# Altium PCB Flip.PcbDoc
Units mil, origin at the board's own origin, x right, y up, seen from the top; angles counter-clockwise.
Board outline 1094.88 x 2000 mil, 4 copper layers (Top Layer, GND, PWR, Bottom Layer), stack 23.756 mil thick; 97 components, 90 nets, 414 pads, 53 vias.
Unrouted connection lines stored in the file: 200.
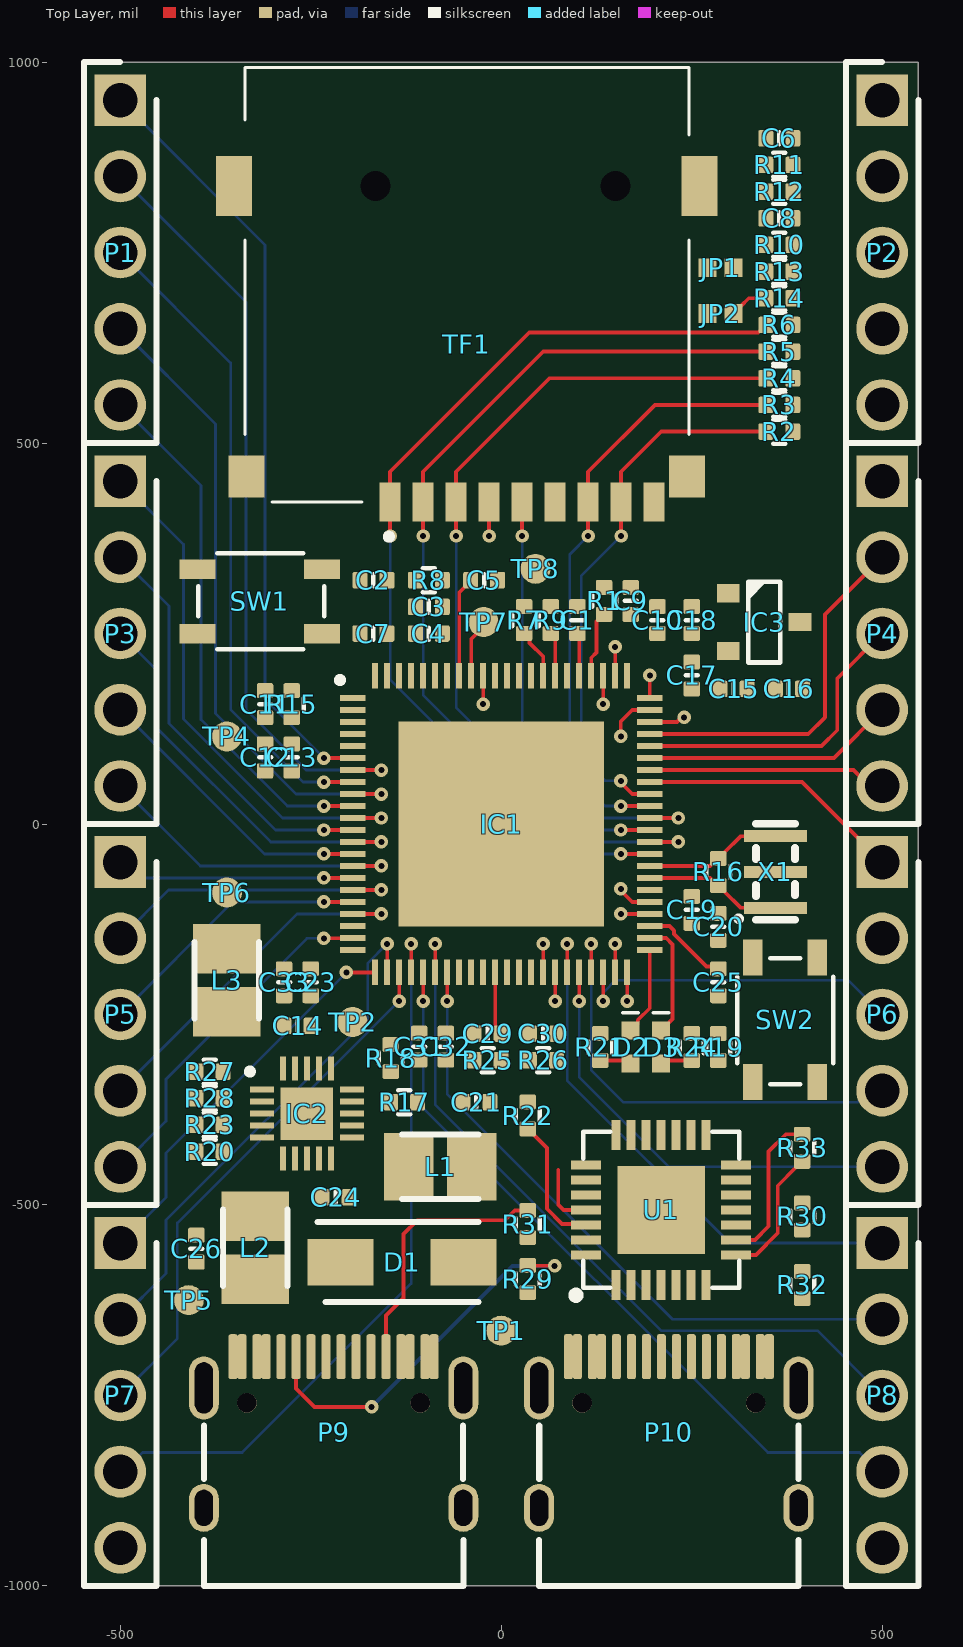
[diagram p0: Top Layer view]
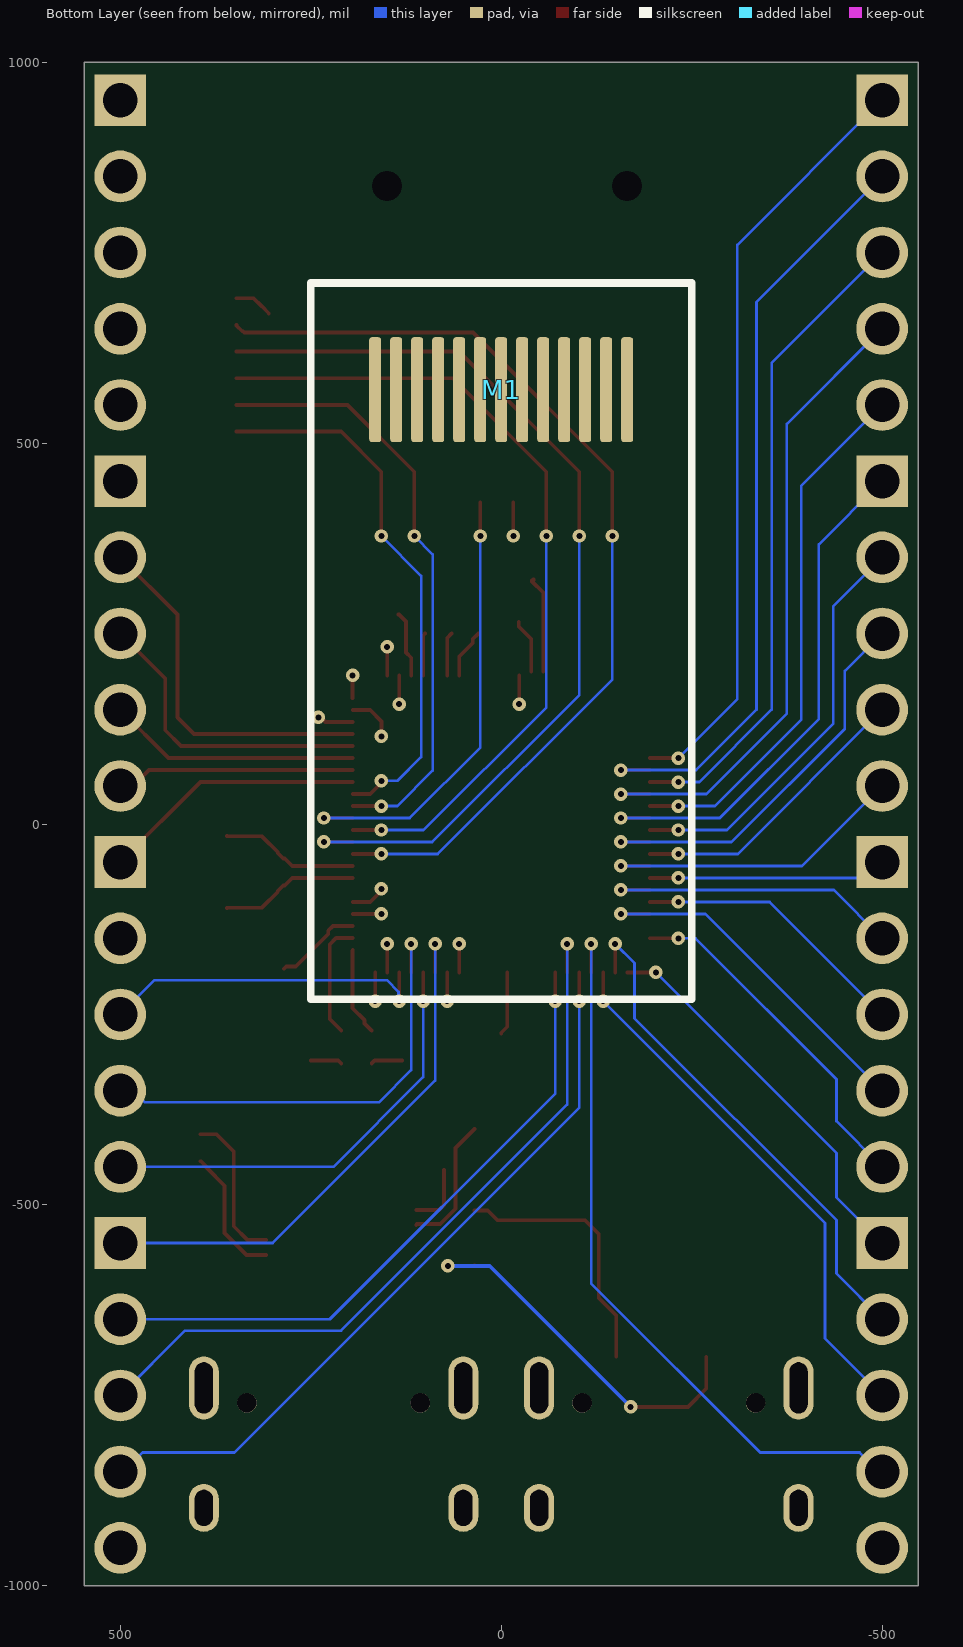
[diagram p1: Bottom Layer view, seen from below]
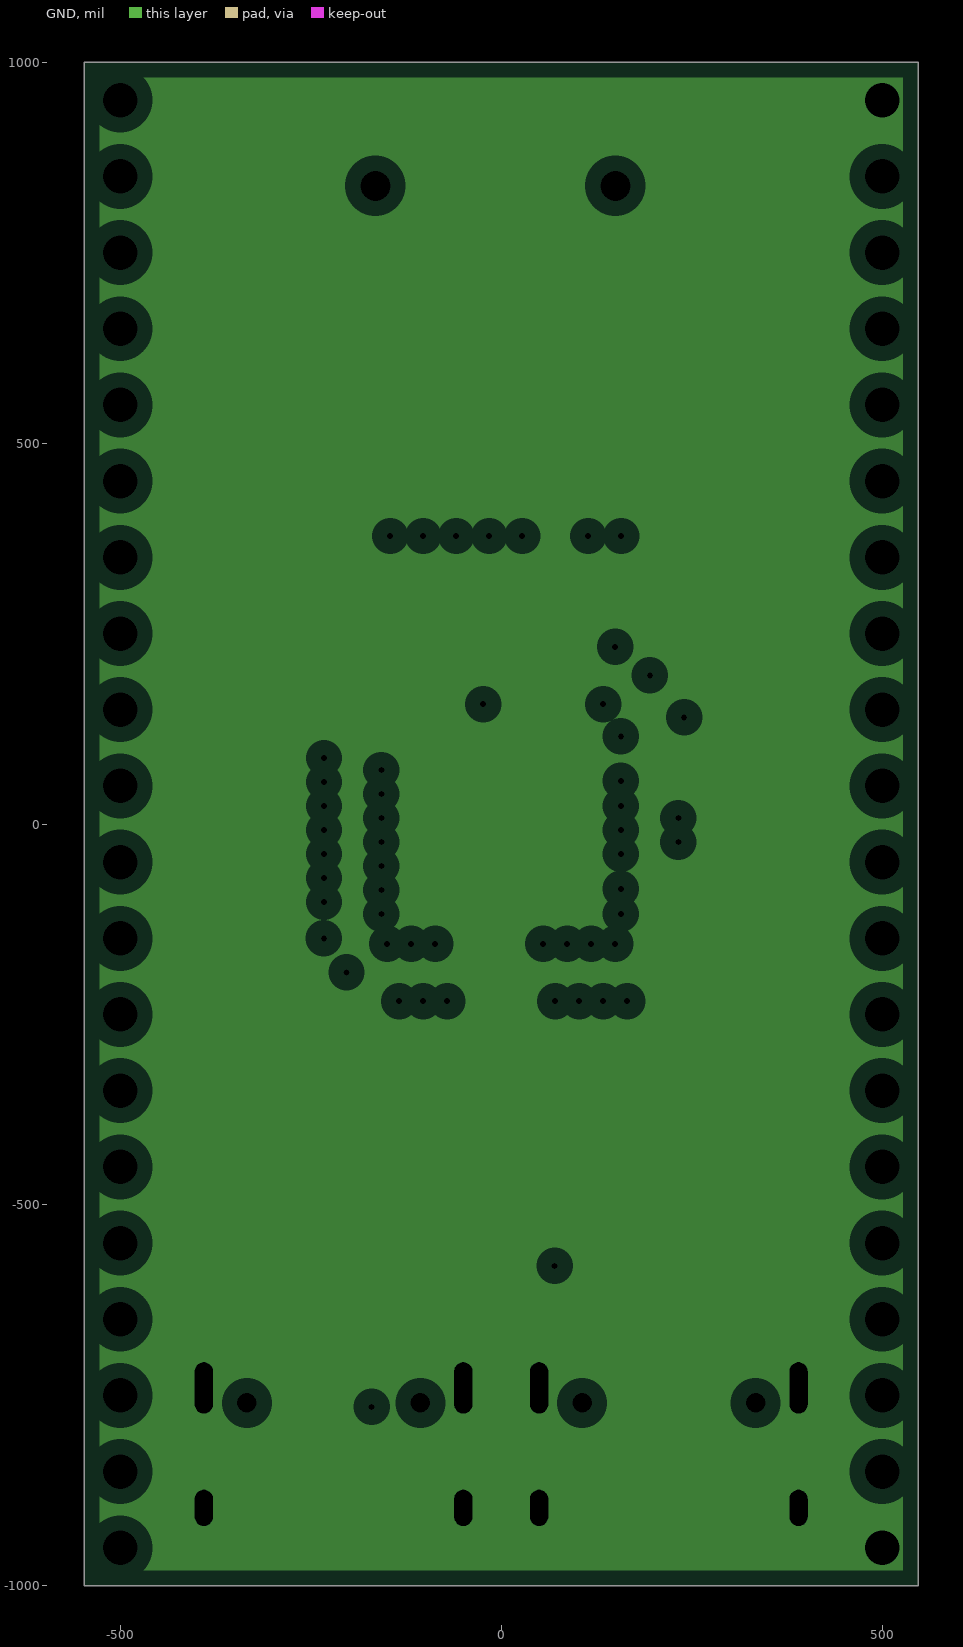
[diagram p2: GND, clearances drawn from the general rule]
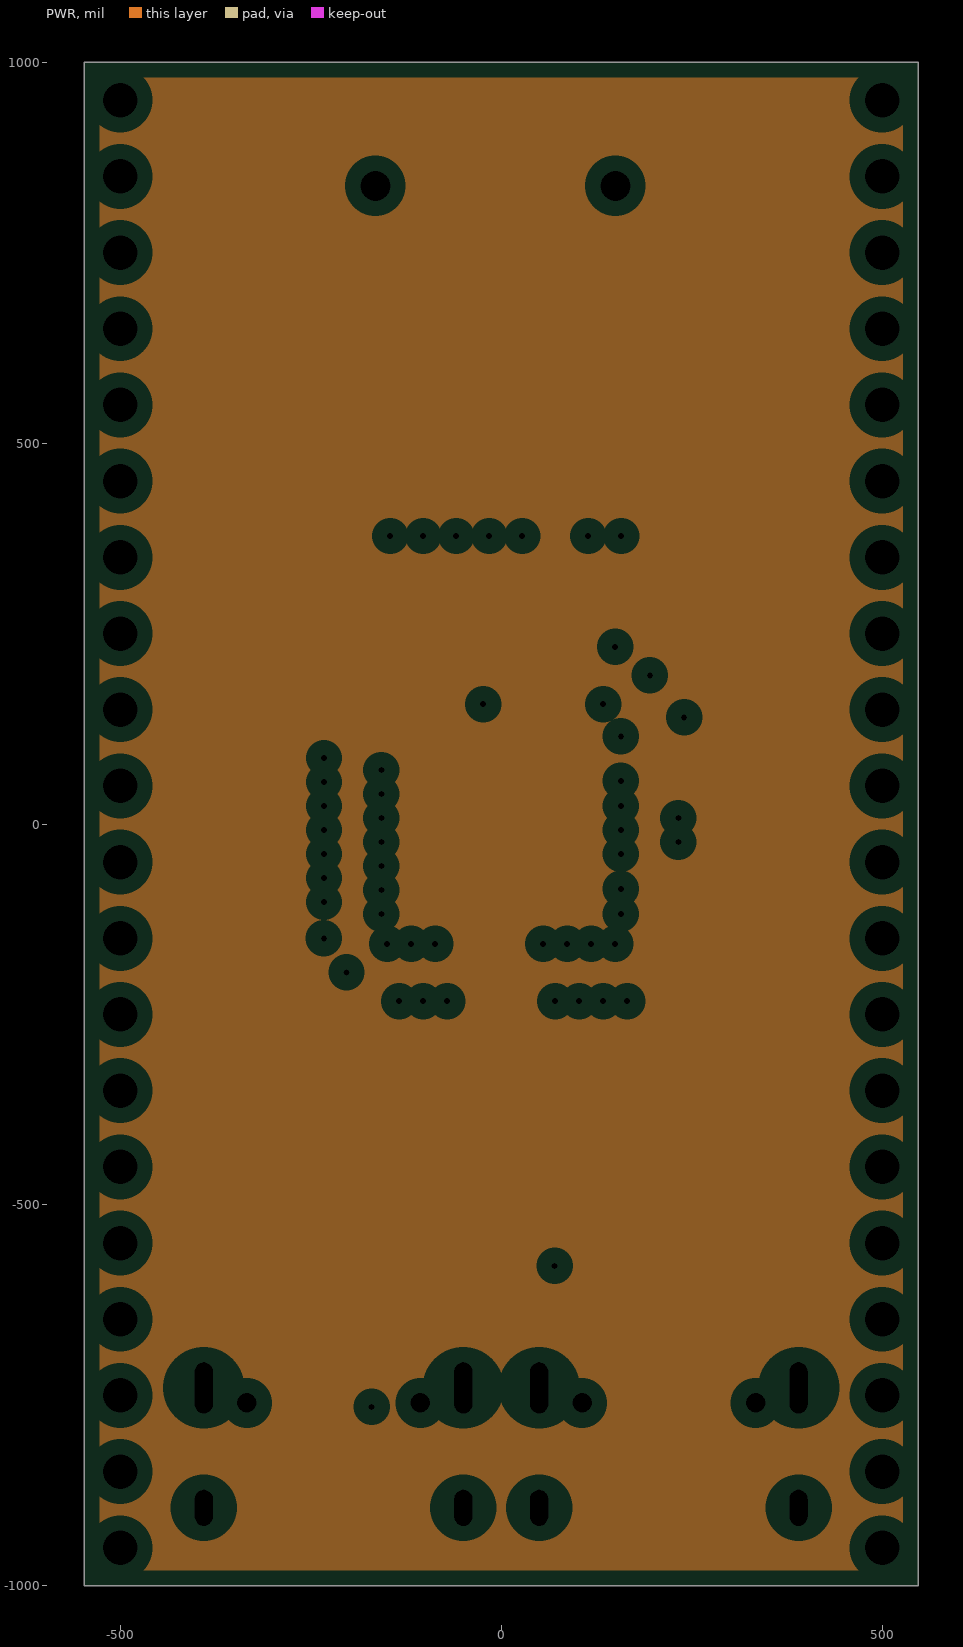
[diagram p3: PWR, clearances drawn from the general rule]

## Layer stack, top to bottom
Top Solder: solder mask 0.4, Solder Resist, Dk 3.5
Top Layer: signal copper 1.4
Dielectric 2: prepreg 2.8, PP-006, Dk 4.1
GND: plane copper 1.378, net GND
Dielectric 1: dielectric 12.6, FR-4, Dk 4.8
PWR: plane copper 1.378
Dielectric 3: prepreg 2.8, PP-006, Dk 4.1
Bottom Layer: signal copper 1.4
Bottom Solder: solder mask 0.4, Solder Resist, Dk 3.5

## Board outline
-547.44,-1000 547.44,-1000 547.44,1000 -547.44,1000

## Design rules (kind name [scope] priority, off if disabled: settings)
Clearance [All] p1: gap=10 ignorepadtopadclearanceinfootprint=FALSE except(0: Arc-Hole Track-Hole SMDPad-Hole THPad-Hole Via-Hole Fill-Hole Poly-Hole Region-Hole Text-Hole)
DiffPairsRouting [All] p1: maxlimit=10 minlimit=10 mostfreqgap=10 toplayer_minwidth=15 toplayer_maxwidth=15 toplayer_prefwidth=15 bottomlayer_minwidth=15 bottomlayer_maxwidth=15 bottomlayer_prefwidth=15 maxuncoupledlength=500
PlaneClearance [All] p1: clearance=20
PlaneConnect [All] p1: planeconnectstyle=Relief reliefexpansion=20 reliefentries=4 reliefconductorwidth=10 reliefairgap=10
PolygonConnect [All] p1: connectstyle=Relief reliefconductorwidth=10 reliefentries=4 polygonreliefangle="90 Angle" airgapwidth=10
RoutingVias [All] p1: holewidth=7.87 width=17.72 viastyle="Through Hole" minholewidth=7.87 minwidth=17.72 maxholewidth=7.87 maxwidth=17.72
SolderMaskExpansion [All] p1: expansion=4 istentingtop=FALSE
Width [All] p1: maxlimit=100 minlimit=3.5 preferedwidth=3.5
27 further rules are at their usual default settings.

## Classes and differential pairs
differential pair USB: +USB_P -USB_N
differential pair USB_CP: +USB_CP_P -USB_CP_N

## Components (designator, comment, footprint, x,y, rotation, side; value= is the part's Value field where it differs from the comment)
C1 "100nF" CAP-0402 100,267.72 r270 top
C2 "10uF" CAP-0402 -167.72,320 r180 top
C3 "100nF" CAP-0402 -95,285 r180 top
C4 "10uF" CAP-0402 -95,250 r0 top
C5 "1uF" CAP-0402 -22.28,320 r180 top
C6 "10uF" CAP-0402 365,900 r0 top
C7 "100nF" CAP-0402 -167.72,250 r180 top
C8 "10uF" CAP-0402 365,795 r0 top
C9 "100nF" CAP-0402 170,292.72 r90 top
C10 "10uF" CAP-0402 205,267.72 r270 top
C11 "1uF" CAP-0402 -310,157.28 r90 top
C12 "10uF" CAP-0402 -310,87.28 r90 top
C13 "100nF" CAP-0402 -275,87.28 r90 top
C14 "100nF" CAP-0402 -267.28,-265 r180 top
C15 "10uF" CAP-0402 305,177.28 r0 top
C16 "1uF" CAP-0402 377.72,177.28 r0 top
C17 "10uF" CAP-0402 250,195 r90 top
C18 "1uF" CAP-0402 250,267.72 r90 top
C19 "100nF" CAP-0402 250,-112.72 r90 top
C20 "10uF" CAP-0402 285,-135 r90 top
C21 "10uF" CAP-0402 -32.72,-365 r0 top
C23 "100nF" CAP-0402 -250,-207.72 r90 top
C24 "10uF" CAP-0402 -217.28,-490 r180 top
C25 "100nF" CAP-0402 285,-207.72 r90 top
C26 "10uF" CAP-0402 -400,-557.28 r270 top
C29 "100nF" CAP-0402 -17.72,-275 r0 top
C30 "100nF" CAP-0402 55,-275 r0 top
C31 "10uF" CAP-0402 -107.72,-292.28 r270 top
C32 "100nF" CAP-0402 -72.72,-292.28 r270 top
C33 "10uF" CAP-0402 -285,-207.72 r90 top
D1 "SS34" DO-214AC/SMA -130,-575 r0 top
D2 "RED" LED-0402 170,-292.72 r90 top
D3 "RED" LED-0402 210,-292.72 r90 top
IC1 "F1C200S" QFN88P_10X10mm 0,0 r0 top
IC2 "EA3036C" QFN3mmx3mm-20 -255,-380 r0 top
IC3 "XC6206P302MR-G" SOT-23-3 345,265 r180 top
JP1 "Select" 选择焊点-0402 288,730 r0 top
JP2 "Select" 选择焊点-0402 288,670 r0 top
L1 "2.2uH" L-1008 -80,-450 r0 top
L2 "2.2uH" L-1008 -322.72,-556.34 r270 top
L3 "2.2uH" L-1008 -360,-205 r90 top
M1 "OLED_12880" OLED_0.78INCH_12880 0,570 r90 bottom locked
P1 "HDR1x5" HDR1X5_2.54_180_BLANK -500,950 r270 top
P2 "HDR1x5" HDR1X5_2.54_180_BLANK 500,950 r270 top
P3 "HDR1x5" HDR1X5_2.54_180_BLANK -500,450 r270 top
P4 "HDR1x5" HDR1X5_2.54_180_BLANK 500,450 r270 top
P5 "HDR1x5" HDR1X5_2.54_180_BLANK -500,-50 r270 top
P6 "HDR1x5" HDR1X5_2.54_180_BLANK 500,-50 r270 top
P7 "HDR1x5" HDR1X5_2.54_180_BLANK -500,-550 r270 top
P8 "HDR1x5" HDR1X5_2.54_180_BLANK 500,-550 r270 top
P9 "TYPE-C-31-M-12" Type-C_16+4P -220,-798.36 r270 top
P10 "TYPE-C-31-M-12" Type-C_16+4P 220,-798.36 r270 top
R1 "10k" R-0402 135,292.72 r90 top
R2 "10k" R-0402 365,515 r0 top
R3 "10k" R-0402 365,550 r0 top
R4 "10k" R-0402 365,585 r0 top
R5 "10k" R-0402 365,620 r0 top
R6 "10k" R-0402 365,655 r0 top
R7 "0R" R-0402 30,267.72 r90 top
R8 "10k" R-0402 -95,320 r0 top
R9 "0R" R-0402 65,267.72 r90 top
R10 "10k" R-0402 365,760 r180 top
R11 "5.1k" R-0402 365,865 r180 top
R12 "560k" R-0402 365,830 r180 top
R13 "10k" R-0402 365,725 r180 top
R14 "10k" R-0402 365,690 r180 top
R15 "22R" R-0402 -275,157.28 r90 top
R16 "1M" R-0402 285,-62.99 r90 top
R17 "510k" R-0402 -127.28,-365 r0 top
R18 "110k" R-0402 -145,-307.28 r270 top
R19 "10k" R-0402 285,-292.72 r90 top
R20 "316k" R-0402 -382.72,-430 r180 top
R21 "5.1k" R-0402 130,-292.72 r270 top
R22 "200R" R-0402 35,-382.72 r270 top
R23 "100k" R-0402 -382.72,-395 r0 top
R24 "5.1k" R-0402 250,-292.72 r270 top
R25 "5.1k" R-0402 -17.72,-310 r0 top
R26 "5.1k" R-0402 55,-310 r0 top
R27 "100k" R-0402 -382.72,-325 r180 top
R28 "100k" R-0402 -382.72,-360 r0 top
R29 "56k" R-0402 35,-597.28 r90 top
R30 "5.1k" R-0402 395,-515 r90 top
R31 "5.1k" R-0402 35,-525 r270 top
R32 "5.1k" R-0402 395,-605 r90 top
R33 "10k" R-0402 395,-425 r270 top
SW1 "KEY" KEY-4P-4.2*3.4*2.5 -316.69,292.32 r180 top
SW2 "KEY" KEY-4P-4.2*3.4*2.5 372.68,-256.69 r90 top
TF1 "TF-01A" TF_1 -45,630 r90 top
TP1 "TestPoint" TestPoint 0,-665 r90 top
TP2 "TestPoint" TestPoint -195,-260 r90 top
TP4 "TestPoint" TestPoint -360,115 r90 top
TP5 "TestPoint" TestPoint -410,-625 r90 top
TP6 "TestPoint" TestPoint -360,-90 r90 top
TP7 "TestPoint" TestPoint -23,265 r90 top
TP8 "TestPoint" TestPoint 45,335 r90 top
U1 "CP2102" QFN28 210,-506.58 r90 top
X1 "24MHz" SMD3213-3P 360,-62.89 r90 top

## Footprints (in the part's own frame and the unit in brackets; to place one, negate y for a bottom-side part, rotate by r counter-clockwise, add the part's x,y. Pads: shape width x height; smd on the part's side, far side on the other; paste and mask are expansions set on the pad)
CAP-0402 [mm]
  rrect25% 0.5x0.55 smd: 1(-0.45,0) 2(0.45,0)
  silkscreen extent 0,-0.2 0,0.2, body extent -0.5,-0.25 0.5,0.25, height 0.6
DO-214AC/SMA [mm]
  rect 2.2x1.55 smd: 1(2.05,0) 2(-2.05,0)
  silkscreen extent -2.83,-1.33 2.55,1.33, body extent -2.55,-1.33 2.55,1.33, height 2.29
HDR1X5_2.54_180_BLANK [mm]
  rect 1.725x1.725 hole 1.15: 1(0,0)
  round 1.725 hole 1.15: 2(2.54,0) 3(5.08,0) 4(7.62,0) 5(10.16,0)
  silkscreen extent -1.27,-1.2 11.43,1.2
KEY-4P-4.2*3.4*2.5 [mm] "SKRPABE010"
  rect 1.2x0.65 smd: 1(-2.075,1.075) 1(2.075,1.075) 2(-2.075,-1.075) 2(2.075,-1.075)
  silkscreen extent -2.15,-1.6 2.05,1.6, body extent -2.35,-1.6 2.25,1.6, height 2.5
L-1008 [mm]
  rect 1.65x2.25 smd: 1(-1.05,0) 2(1.05,0)
  silkscreen extent -1.28,-1.07 1.28,1.07, body extent -1.28,-1.07 1.28,1.07, height 1.2
LED-0402 [mm]
  rect 0.6x0.6 smd: 1(-0.55,0) 2(0.55,0)
  silkscreen extent 1.14,-0.25 1.14,0.25, body extent -0.5,-0.25 0.5,0.25, height 0.5
OLED_0.78INCH_12880 [mm]
  rrect50% 3.5x0.4 smd: 1(0,-4.2) 2(0,-3.5) 3(0,-2.8) 4(0,-2.1) 5(0,-1.4) 6(0,-0.7) 7(0,0) 8(0,0.7) 9(0,1.4) 10(0,2.1) 11(0,2.8) 12(0,3.5) 13(0,4.2)
  silkscreen extent -20.32,-6.35 3.56,6.35, body extent -20.18,-6.25 7.54,6.25, height 1.55
QFN3mmx3mm-20 [mm]
  rect 0.8x0.2 smd: 1(-1.5,0.8) 2(-1.5,0.4) 3(-1.5,0) 4(-1.5,-0.4) 5(-1.5,-0.8) 11(1.5,-0.8) 12(1.5,-0.4) 13(1.5,0) 14(1.5,0.4) 15(1.5,0.8)
  rect 0.2x0.8 smd: 6(-0.8,-1.5) 7(-0.4,-1.5) 8(0,-1.5) 9(0.4,-1.5) 10(0.8,-1.5) 16(0.8,1.5) 17(0.4,1.5) 18(0,1.5) 19(-0.4,1.5) 20(-0.8,1.5)
  rect 1.75x1.75 smd: 21(0,0)
  silkscreen extent -2,1.3 -1.8,1.5, body extent -1.55,-1.55 1.55,1.55, height 0.8
QFN28 [mm]
  rect 1x0.3 smd: 1(-2.5,1.5) 2(-2.5,1) 3(-2.5,0.5) 4(-2.5,0) 5(-2.5,-0.5) 6(-2.5,-1) 7(-2.5,-1.5) 15(2.5,-1.5) 16(2.5,-1) 17(2.5,-0.5) 18(2.5,0) 19(2.5,0.5) 20(2.5,1) 21(2.5,1.5)
  rect 0.3x1 smd: 8(-1.5,-2.5) 9(-1,-2.5) 10(-0.5,-2.5) 11(0,-2.5) 12(0.5,-2.5) 13(1,-2.5) 14(1.5,-2.5) 22(1.5,2.5) 23(1,2.5) 24(0.5,2.5) 25(0,2.5) 26(-0.5,2.5) 27(-1,2.5) 28(-1.5,2.5)
  rect 2.921x2.921 smd paste-3.2: 29(0,0)
  silkscreen extent -2.97,-2.6 2.6,2.97, body extent -2.5,-2.5 2.5,2.5, height 1
QFN88P_10X10mm [mm]
  rect 0.85x0.2 smd: 1(-4.95,4.2) 2(-4.95,3.8) 3(-4.95,3.4) 4(-4.95,3) 5(-4.95,2.6) 6(-4.95,2.2) 7(-4.95,1.8) 8(-4.95,1.4) 9(-4.95,1) 10(-4.95,0.6) 11(-4.95,0.2) 12(-4.95,-0.2) 13(-4.95,-0.6) 14(-4.95,-1) 15(-4.95,-1.4) 16(-4.95,-1.8) 17(-4.95,-2.2) 18(-4.95,-2.6) 19(-4.95,-3) 20(-4.95,-3.4) 21(-4.95,-3.8) 22(-4.95,-4.2) 45(4.95,-4.2) 46(4.95,-3.8) 47(4.95,-3.4) 48(4.95,-3) 49(4.95,-2.6) 50(4.95,-2.2) 51(4.95,-1.8) 52(4.95,-1.4) 53(4.95,-1) 54(4.95,-0.6) 55(4.95,-0.2) 56(4.95,0.2) 57(4.95,0.6) 58(4.95,1) 59(4.95,1.4) 60(4.95,1.8) 61(4.95,2.2) 62(4.95,2.6) 63(4.95,3) 64(4.95,3.4) 65(4.95,3.8) 66(4.95,4.2)
  rect 0.2x0.85 smd: 23(-4.2,-4.95) 24(-3.8,-4.95) 25(-3.4,-4.95) 26(-3,-4.95) 27(-2.6,-4.95) 28(-2.2,-4.95) 29(-1.8,-4.95) 30(-1.4,-4.95) 31(-1,-4.95) 32(-0.6,-4.95) 33(-0.2,-4.95) 34(0.2,-4.95) 35(0.6,-4.95) 36(1,-4.95) 37(1.4,-4.95) 38(1.8,-4.95) 39(2.2,-4.95) 40(2.6,-4.95) 41(3,-4.95) 42(3.4,-4.95) 43(3.8,-4.95) 44(4.2,-4.95) 67(4.2,4.95) 68(3.8,4.95) 69(3.4,4.95) 70(3,4.95) 71(2.6,4.95) 72(2.2,4.95) 73(1.8,4.95) 74(1.4,4.95) 75(1,4.95) 76(0.6,4.95) 77(0.2,4.95) 78(-0.2,4.95) 79(-0.6,4.95) 80(-1,4.95) 81(-1.4,4.95) 82(-1.8,4.95) 83(-2.2,4.95) 84(-2.6,4.95) 85(-3,4.95) 86(-3.4,4.95) 87(-3.8,4.95) 88(-4.2,4.95)
  rect 6.84x6.84 smd: 89(0,0)
  silkscreen extent -5.47,4.7 -5.28,4.9, body extent -5.05,-5.05 5.05,5.05, height 0.9
R-0402 [mm]
  rrect25% 0.5x0.55 smd: 1(-0.45,0) 2(0.45,0)
  silkscreen extent -0.2,-0.4 0.2,0.4, body extent -0.5,-0.25 0.5,0.25, height 0.6
SMD3213-3P [mm]
  rect 0.4x2.1 smd: 1(-1.2,0) 2(0,0) 3(1.2,0)
  silkscreen extent -1.61,-0.65 1.6,1.27, body extent -1.6,-0.65 1.6,0.65, height 0.7
SOT-23-3 [mil]
  rect 30x24 smd: 1(47,-38) 2(47,38) 3(-47,0)
  silkscreen extent -21,-53 21,53, body extent -55,-57 55,57, height 51
TestPoint [mm]
  round 1 smd: 1(0,0)
TF_1 [mm]
  rect 1.3x0.7 smd: 1(-5.275,2.56) 2(-5.275,1.46) 3(-5.275,0.36) 4(-5.275,-0.74) 5(-5.275,-1.84) 6(-5.275,-2.94) 7(-5.275,-4.04) 8(-5.275,-5.14) 9(-5.275,-6.24)
  rect 1.4x1.2 smd: 10(-4.425,-7.34) 13(-4.425,7.34)
  rect 2x1.2 smd: 11(5.275,-7.76) 12(5.275,7.76)
  round 0.5 hole 1 unplated: 14(5.275,-4.95) 15(5.275,3.05)
  silkscreen extent -6.53,-7.4 9.23,7.4, body extent -5.9,-7.7 11.92,8.4, height 2.05
Type-C_16+4P [mm]
  round 0.65 hole 0.65: 0(-0.98,2.89) 0(-0.98,-2.89)
  oval 1.6x1 hole 0.6 slot 1.2 at 0 deg: 1(2.52,4.325) 2(2.52,-4.325)
  oval 2.1x1 hole 0.6 slot 1.7 at 0 deg: 3(-1.48,-4.325) 4(-1.48,4.325)
  rrect50% 1.5x0.3 smd: A1(-2.52,-3.35) A4(-2.52,-2.55) A5(-2.52,-1.25) A6(-2.52,-0.25) A7(-2.52,0.25) A8(-2.52,1.25) A9(-2.52,2.55) A12(-2.52,3.35) B1(-2.52,3.05) B4(-2.52,2.25) B5(-2.52,1.75) B6(-2.52,0.75) B7(-2.52,-0.75) B8(-2.52,-1.75) B9(-2.52,-2.25) B12(-2.52,-3.05)
  silkscreen extent -0.22,-4.33 5.12,4.33, body extent -2.57,-4.48 5.18,4.48, height 3.26
选择焊点-0402 [mm]
  rect 0.6x0.62 smd: 1(-0.432,0) 2(0.432,0)

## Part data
C1 C2 C3 C4 C5 C6 C7 C8 C9 C10 C11 C12 C13 C14 C15 C16 C17 C18 C19 C20 C21 C23 C24 C25 C26 C29 C30 C31 C32 C33: library part CAP, "贴片电容", Package=0402, SuppliersPartNumber=C52923
D1: library part DIODE, "肖特基二极管", Package=SMA(DO-214AC), SuppliersPartNumber=C22452
D2 D3: library part LED, "发光二极管", Package=0603, SuppliersPartNumber=C2290
IC1: library part F1C100S/F1C200S, "SOC", Manufacturer_Name="Allwinner Technology"
IC2: "EA3036 is a 3CH power management IC for applications powered by one Li-Ion battery or a DC 5V adapter."
IC3: library part XC6206, "LDO", Manufacturer_Name=Torex, Manufacturer_Part_Number=XC6206P122MR-G, Mouser Part Number=865-XC6206P122MR-G
JP1 JP2: "选择焊点"
L1 L2 L3: library part INDUCTOR, "SRN2512-2R2M", Package=0402, SuppliersPartNumber=C32041
M1: "OLED屏"
P1 P2 P3 P4 P5 P6 P7 P8: library part HDR1x5_2.54, "Header", Manufacturer_Name="FCI Electronics", Manufacturer_Part_Number=10129378-905001BLF, Mouser Part Number=649-1012937890501BLF
P9 P10: library part USB_Type-C_16+4P, "USB Type-C 座子"
R1 R2 R3 R4 R5 R6 R7 R8 R9 R10 R11 R12 R13 R14 R15 R16 R19 R21 R22 R24 R25 R26 R29 R30 R31 R32 R33: library part RES, "贴片电阻", Package=0805, SuppliersPartNumber=C17798
R17 R18: library part RES, "RC0402FR-07510KL", Package=0805, SuppliersPartNumber=C17798
R20: library part RES, "RC0402FR-07316KL", Package=0805, SuppliersPartNumber=C17798
R23 R27 R28: library part RES, "RC0402FR-07100KL", Package=0805, SuppliersPartNumber=C17798
SW1 SW2: "按键开关"
TF1: library part TF卡座_8脚自弹, "与TF-01A封装相似则可替换"
TP1 TP2 TP4 TP5 TP6 TP7 TP8: "测试点"
U1: "CP2102-GMR"
X1: library part XTAL, "村田无源晶振"

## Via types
v1: diameter 17.72, hole 7.87, Top Layer to Bottom Layer, 53 vias

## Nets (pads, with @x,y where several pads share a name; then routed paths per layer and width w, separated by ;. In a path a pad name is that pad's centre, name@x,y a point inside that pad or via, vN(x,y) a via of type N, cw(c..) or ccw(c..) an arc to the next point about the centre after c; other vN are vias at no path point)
ADC0: IC1.79 P2.3 | length 37.7
  Top Layer w5: v1(-23.62,157.19) IC1.79
AGND: C3.1 C4.2 C5.1 IC1.74 IC1.82 R7.1 R8.2 TP8.1 | length 65.5
  Top Layer w5: R7.1 37.31,242.69 37.31,237.47 55.12,219.66 IC1.74
AVCC_3V0: C17.2 C18.1 IC1.80 IC3.2 TP7.1 | length 71.9
  Top Layer w5: IC1.80@-39.37,199.88 -39.37,242.92 -23,259.29 TP7.1
GND: C1.1 C2.1 C6.2 C7.1 C8.2 C9.2 C10.1 C11.1 C12.1 C13.1 C14.1 C15.1 C16.2 C17.1 C18.2 C19.1 C20.1 C21.1 C23.1 C24.1 C25.1 C26.1 C30.2 C31.1 C32.1 C33.1 IC1.89 IC2.1 IC2.4 IC2.5 IC2.12 IC2.13 IC2.15 IC2.17 IC2.21 IC3.1 M1.7 M1.9 M1.12 P2.1 P8.5 P9.1 P9.2 P9.3 P9.4 P9.A1 P9.A12 P9.B1 P9.B12 P10.1 P10.2 P10.3 P10.4 P10.A1 P10.A12 P10.B1 P10.B12 R7.2 R12.1 R18.1 R23.1 R26.2 R28.1 R30.2 R31.2 R32.2 SW1.2 SW2.2 TF1.6 TF1.9 TF1.10 TF1.11 TF1.12 TF1.13 U1.3 U1.29 X1.2
KEY_USR: C25.2 IC1.47 R19.1 SW2.1 | length 116
  Top Layer w5: IC1.47 220.86,-133.86 227,-140 227,-144.49 269.6,-187.1 282.1,-187.1 C25.2
LED_SYS: D3.2 IC1.46 | length 152.9
  Top Layer w5: IC1.46 216.61,-149.61 225,-158 225,-256.06 D3.2
LED_USR: D2.2 IC1.45 | length 116.1
  Top Layer w5: D2.2 179.31,-261.75 179.31,-257.46 195,-241.77 195,-166.79 194.88,-166.67 IC1.45
NetC3_2: C3.2 C4.1 IC1.83 R8.1
NetC5_2: C5.2 IC1.81 | length 127.4
  Top Layer w5: IC1.81@-55.12,199.88 -55.12,303.9 -40,319.02 C5.2 ; C5.2@-42.28,320 C5.2@-42.28,320.98
NetC6_1: C6.1 M1.3
NetC7_2: C7.2 IC1.70 R1.1 SW1.1 | length 87.7
  Top Layer w5: IC1.70 118.11,218.11 125,225 125,265.98 134.02,275 R1.1
NetC8_1: C8.1 M1.8 R10.2
NetC11_2: C11.2 IC1.2 R15.2
NetC29_2: C29.2 C30.1 IC1.33 R25.2 R26.1 | length 83.4
  Top Layer w5: IC1.33 -7.87,-266.14 0,-274.02 C29.2
NetD2_A: D2.1 R21.2 | length 41.6
  Top Layer w5: R21.2 166.06,-310.43 D2.1
NetD3_A: D3.1 R24.2 | length 41.6
  Top Layer w5: D3.1 213.94,-310.43 R24.2
NetIC1_3: IC1.3 R15.1
NetIC1_51: IC1.51 R16.1 X1.1 | length 182
  Top Layer w5: IC1.51 274.17,-70.87 284.02,-80.71 285.98,-80.71 293.33,-88.05 293.33,-89.04 314.09,-109.8 359.46,-109.8 X1.1@360,-110.34
NetIC1_52: IC1.52 R16.2 X1.3 | length 182
  Top Layer w5: IC1.52 274.17,-55.12 284.02,-45.28 285.98,-45.28 293.33,-37.93 293.33,-36.95 314.09,-16.19 359.46,-16.19 X1.3
NetIC1_73: IC1.73 R9.1 | length 57.5
  Top Layer w5: R9.1 70.87,244.13 IC1.73
NetIC2_2: IC2.2 R27.1 R28.2
NetIC2_3: IC2.3 R20.1 R23.2
NetIC2_6: IC2.6 L2.1
NetIC2_11: IC2.11 L1.1
NetIC2_14: IC2.14 R17.1 R18.2
NetIC2_20: IC2.20 L3.1
NetJP1_2: JP1.2 M1.10 R13.2
NetJP2_2: JP2.2 M1.11 R14.2 | length 50.8
  Top Layer w5: JP2.2 305,670.39 314.31,679.7 314.7,679.7 325,690 R14.2
NetM1_5: M1.5 R11.2
NetM1_6: M1.6 R12.2
NetP9_B5: P9.B5 R31.1 | length 346.4
  Top Layer w5: P9.B5 -151.1,-645 -128.05,-621.95 -128.05,-538.05 -110,-520 5,-520 17.72,-507.28 R31.1
NetP10_A5: P10.A5 R30.1
NetP10_B5: P10.B5 R32.1
NetR22_2: R22.2 U1.26 | length 175.3
  Top Layer w5: R22.2 60,-425.43 60,-505 80,-525 110.31,-525 U1.26
NetR33_1: R33.1 U1.9 | length 201.4
  Top Layer w5: U1.9 333.05,-545.95 351,-528 351,-430 373.72,-407.28 R33.1
PA0/TOUCH_X1: IC1.66 P2.4 | length 29.7
  Top Layer w5: IC1.66 195,165.47 v1(195,195)
PA1/TOUCH_X2: IC1.65 P2.5 | length 61.8
  Top Layer w5: v1@156.97,116.97 156.97,134.67 171.93,149.63 IC1.65
  other v1: 157.21,115
PA2/TOUCH_Y1: IC1.64 P4.1 | length 47.7
  Top Layer w5: IC1.64 230.71,133.86 236.85,140 v1(240,140)
PA3/TOUCH_Y2: IC1.63 P4.2 | length 480.3
  Top Layer w5: IC1.63 403.11,118.11 425,140 425,275 P4.2
PC0/SPI0_CLK: IC1.59 P6.1 | length 348.7
  Top Layer w5: IC1.59 394.88,55.12 P6.1
PC1/SPI0_CS: IC1.60 P4.5 | length 313.8
  Top Layer w5: IC1.60 462.24,70.87 483.1,50 P4.5
PC2/SPI0_MISO: IC1.61 P4.4 | length 331.4
  Top Layer w5: IC1.61 436.61,86.61 P4.4
PC3/SPI0_MOSI: IC1.62 P4.3 | length 406.1
  Top Layer w5: IC1.62 420.36,102.36 441,123 441,191 P4.3
PD0: IC1.6 P1.1 | length 1011.8
  Top Layer w5: v1(-232.57,86.61) IC1.6
  Bottom Layer w3.5: P1.1 -310,760 -310,164.04 v1(-232.57,86.61)
PD1: IC1.7 P1.2 | length 1016.6
  Top Layer w5: IC1.7 v1(-157.19,70.87)
  Bottom Layer w3.5: P1.2 -335,685 -335,150 -255.87,70.87 v1(-157.19,70.87)
PD2: IC1.8 P1.3 | length 859.5
  Top Layer w5: v1(-232.57,55.12) IC1.8
  Bottom Layer w3.5: P1.3 -355,605 -355,150 -260.12,55.12 v1(-232.57,55.12)
PD3/UART1_RX: IC1.9 P1.4 | length 856
  Top Layer w5: IC1.9 v1(-157.19,39.37)
  Bottom Layer w3.5: P1.4 -375,525 -375,145 -269.37,39.37 v1(-157.19,39.37)
PD4/UART1_TX: IC1.10 P1.5 | length 703
  Top Layer w5: v1(-232.57,23.62) IC1.10
  Bottom Layer w3.5: P1.5 -394,444 -394,137 -280.62,23.62 v1(-232.57,23.62)
PD5: IC1.11 P3.1 | length 697.8
  Top Layer w5: IC1.11 v1(-157.19,7.87)
  Bottom Layer w3.5: P3.1 -417,367 -417,138 -286.87,7.87 v1(-157.19,7.87)
PD6: IC1.12 P3.2 | length 543.6
  Top Layer w5: v1(-232.57,-7.87) IC1.12
  Bottom Layer w3.5: P3.2 -436,286 -436,132 -296.13,-7.87 v1(-232.57,-7.87)
PD7: IC1.13 P3.3 | length 538.4
  Top Layer w5: IC1.13 v1(-157.19,-23.62)
  Bottom Layer w3.5: P3.3 -451,201 -451,125 -302.38,-23.62 v1(-157.19,-23.62)
PD8: IC1.14 P3.4 | length 383.6
  Top Layer w5: v1(-232.57,-39.37) IC1.14
  Bottom Layer w3.5: P3.4 -310.63,-39.37 v1(-232.57,-39.37)
PD9: IC1.15 P3.5 | length 424
  Top Layer w5: IC1.15 v1(-157.19,-55.12)
  Bottom Layer w3.5: P3.5 -394.88,-55.12 v1(-157.19,-55.12)
PD10: IC1.16 P5.1 | length 313.8
  Top Layer w5: v1(-232.57,-70.87) IC1.16
  Bottom Layer w3.5: P5.1 -479.13,-70.87 v1(-232.57,-70.87)
PD11: IC1.17 P5.2 | length 406.8
  Top Layer w5: IC1.17 v1(-157.19,-86.61)
  Bottom Layer w3.5: P5.2 -436.61,-86.61 v1(-157.19,-86.61)
PD12: IC1.18 P5.3 | length 366.3
  Top Layer w5: v1(-232.57,-102.36) IC1.18
  Bottom Layer w3.5: P5.3 -352.36,-102.36 v1(-232.57,-102.36)
PD13/UART2_TX: IC1.19 P5.4 | length 476.5
  Top Layer w5: IC1.19 v1(-157.19,-118.11)
  Bottom Layer w3.5: P5.4 -268.11,-118.11 v1(-157.19,-118.11)
PD14/UART2_RX: IC1.21 P5.5 | length 461.5
  Top Layer w5: v1(-232.69,-150) IC1.21@-195,-150
  Bottom Layer w3.5: P5.5 -440,-390 -440,-335 -255,-150 v1(-232.69,-150)
PD15/I2C2_CLK: IC1.23 P7.1 | length 515.8
  Top Layer w5: v1(-203.04,-194.88) IC1.23
  Bottom Layer w3.5: P7.1 -440,-490 -440,-431.84 v1(-203.04,-194.88)
PD16/I2C2_SDA: IC1.24 P7.2 | length 675.6
  Top Layer w5: IC1.24 v1(-149.61,-157.19)
  Bottom Layer w3.5: P7.2 -440,-590 -440,-520 -175,-255 -175,-182.59 v1(-149.61,-157.19)
PD17: IC1.25 P7.3 | length 706.8
  Top Layer w5: v1(-133.86,-232.57) IC1.25
  Bottom Layer w3.5: P7.3 -425,-675 -425,-523.71 v1(-133.86,-232.57)
PD18: IC1.26 P7.4 | length 967.8
  Top Layer w5: IC1.26 v1(-118.11,-157.19)
  Bottom Layer w3.5: P7.4 -495.51,-850 -470.51,-825 -340,-825 -118.11,-603.11 v1(-118.11,-157.19)
PD19: IC1.27 P8.4 | length 977.8
  Top Layer w5: v1(-102.36,-232.57) IC1.27
  Bottom Layer w3.5: v1(-102.36,-232.57) -102.36,-372.64 350,-825 470.51,-825 495.51,-850 P8.4
PD20: IC1.28 P8.3 | length 993.6
  Top Layer w5: IC1.28 v1(-86.61,-157.19)
  Bottom Layer w3.5: v1(-86.61,-157.19) -86.61,-368.39 210,-665 415,-665 P8.3
PD21: IC1.29 P8.2 | length 852.7
  Top Layer w5: v1(-70.87,-232.57) IC1.29
  Bottom Layer w3.5: v1(-70.87,-232.57) -70.87,-354.13 225,-650 P8.2
PE6/PWM1: IC1.43 P6.2 | length 37.7
  Top Layer w5: IC1.43 v1(149.61,-157.19)
PE7/SPI1_CS: IC1.42 P6.3 | length 440.6
  Top Layer w5: v1(133.86,-232.57) IC1.42
  Bottom Layer w3.5: v1(133.86,-232.57) 134.71,-231.72 134.71,-220.29 150,-205 455,-205 P6.3
PE8/SPI1_MOSI: IC1.41 P6.4 | length 609.1
  Top Layer w5: IC1.41 v1(118.11,-157.19)
  Bottom Layer w3.5: v1(118.11,-157.19) 118.11,-323.11 160,-365 467.98,-365 482.98,-350 P6.4
PE9/SPI1_CLK: IC1.40 P6.5 | length 583.8
  Top Layer w5: v1(102.36,-232.57) IC1.40
  Bottom Layer w3.5: v1(102.36,-232.57) 102.36,-332.36 220,-450 P6.5
PE10/SPI1_MISO: IC1.39 P8.1 | length 718.9
  Top Layer w5: IC1.39 v1(86.61,-157.19)
  Bottom Layer w3.5: v1(86.61,-157.19) 86.61,-336.61 300,-550 P8.1
PE11/I2C0_CLK: IC1.38 JP1.1 | length 37.7
  Top Layer w5: v1(70.87,-232.57) IC1.38
PE12/I2C0_SDA: IC1.37 JP2.1 | length 37.7
  Top Layer w5: IC1.37 v1(55.12,-157.19)
SDC0_CLK: IC1.56 TF1.5 | length 603
  Top Layer w5: v1(27.44,378) TF1.5 ; IC1.56 v1(232.57,7.87)
  Bottom Layer w3.5: v1(27.44,378) 27.44,100.56 120.13,7.87 v1(232.57,7.87)
SDC0_CMD: IC1.55 R4.1 TF1.3 | length 1087.2
  Top Layer w5: v1(-59.17,378) TF1.3 -59.17,462.36 63.46,585 R4.1 ; v1(157.19,-7.87) IC1.55
  Bottom Layer w3.5: v1(-59.17,378) -59.17,153.17 101.87,-7.87 v1(157.19,-7.87)
SDC0_D0: IC1.57 R3.1 TF1.7 | length 795.9
  Top Layer w5: v1(114.06,378) TF1.7 114.06,462.36 201.69,550 R3.1 ; v1(157.19,23.62) IC1.57
  Bottom Layer w3.5: v1(114.06,378) 90,353.94 90,70 136.38,23.62 v1(157.19,23.62)
SDC0_D1: IC1.58 R2.1 TF1.8 | length 719.4
  Top Layer w5: v1(157.21,56.75) 157.21,54.1 171.95,39.37 IC1.58 ; v1(157.36,378) TF1.8 157.36,462.36 210,515 R2.1
  Bottom Layer w3.5: v1(157.21,56.75) 136.25,56.75 105,88 105,325.64 v1(157.36,378)
SDC0_D2: IC1.53 R6.1 TF1.1 | length 1281.6
  Top Layer w5: v1(-145.79,378) TF1.1 -145.79,462.36 36.85,645 337.01,645 338.69,646.67 339.94,646.67 347.28,654.02 R6.1 ; v1(157.19,-39.37) IC1.53
  Bottom Layer w3.5: v1(-145.79,378) -145.79,189.79 83.37,-39.37 v1(157.19,-39.37)
SDC0_D3: IC1.54 R5.1 TF1.2 | length 1260.7
  Top Layer w5: v1(-102.48,378) TF1.2 -102.48,462.36 55.16,620 R5.1 ; IC1.54 v1(232.57,-23.62)
  Bottom Layer w3.5: v1(-102.48,378) -102.48,169.48 90.62,-23.62 v1(232.57,-23.62)
UART0_RX: IC1.49 R22.1 | length 46.4
  Top Layer w5: v1(157.19,-85) 157.19,-87.65 171.93,-102.38 IC1.49
UART0_TX: IC1.48 U1.25 | length 123.1
  Top Layer w5: 75,-453.86 75,-500 81.58,-506.58 U1.25 ; v1(157.19,-118.11) IC1.48
USB_CP_N: P10.A7 P10.B7 U1.5
USB_CP_P: P10.A6 P10.B6 U1.4
USB_ID: IC1.44 P9.A5 R29.2 | length 540.4
  Top Layer w5: P9.A5 -269.21,-740.79 -245,-765 v1(-170,-765) ; R29.2 35.22,-579.78 69.78,-579.78 v1(70,-580) ; v1(165.35,-232.57) IC1.44
  Bottom Layer w5: v1(-170,-765) 15,-580 v1(70,-580)
USB_N: IC1.68 P9.A7 P9.B7 | length 37.7
  Top Layer w5: IC1.68 v1(149.61,232.57)
USB_P: IC1.69 P9.A6 P9.B6 | length 37.7
  Top Layer w5: v1(133.86,157.19) IC1.69
VBUS: D1.1 P9.A4 P9.A9 P9.B4 P9.B9 P10.A4 P10.A9 P10.B4 P10.B9 R29.1 R33.2 TP1.1 U1.7 U1.8 | length 174.5
  Top Layer w5: U1.8 334.37,-565.63 363,-537 363,-474.72 386.67,-451.04 386.67,-450.06 394.02,-442.72 R33.2
VCC_1V2: C1.2 C23.2 C33.2 IC1.22 IC1.35 IC1.71 L3.2 R27.2 TP6.1 | length 56.1
  Top Layer w5: C1.2 102.36,247.64 IC1.71
VCC_2V5: C26.2 C29.1 C31.2 C32.2 IC1.30 IC1.31 IC1.32 IC1.34 IC1.36 L2.2 R20.2 R25.1 TP5.1
VCC_3V3: C2.2 C9.1 C10.2 C12.2 C13.2 C19.2 C20.2 C21.2 IC1.4 IC1.5 IC1.20 IC1.50 IC1.67 L1.2 M1.4 P7.5 R1.2 R2.2 R3.2 R4.2 R5.2 R6.2 R9.2 R10.1 R11.1 R13.1 R14.1 R17.2 R19.2 R21.1 R24.1 TF1.4 TP4.1 | length 44.3
  Top Layer w5: v1(-15.87,378) TF1.4
VCC_5V: C14.2 C15.2 C16.1 C24.2 D1.2 IC2.7 IC2.8 IC2.9 IC2.10 IC2.16 IC2.18 IC2.19 IC3.3 M1.2 P2.2 TP2.1
pads on no net: IC1.1 IC1.72 IC1.75 IC1.76 IC1.77 IC1.78 IC1.84 IC1.85 IC1.86 IC1.87 IC1.88 M1.1 M1.13 P9.0 P9.A8 P9.B8 P10.0 P10.A8 P10.B8 TF1.14 TF1.15 U1.1 U1.2 U1.6 U1.10 U1.11 U1.12 U1.13 U1.14 U1.15 U1.16 U1.17 U1.18 U1.19 U1.20 U1.21 U1.22 U1.23 U1.24 U1.27 U1.28

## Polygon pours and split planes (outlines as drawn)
GND on GND (split plane): 527.34,-979.9 -527.34,-979.9 -527.34,979.9 527.34,979.9
no net on PWR (split plane): 527.34,-979.9 -527.34,-979.9 -527.34,979.9 527.34,979.9

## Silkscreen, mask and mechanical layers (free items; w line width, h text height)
Mechanical 1:
  the board outline again, w5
